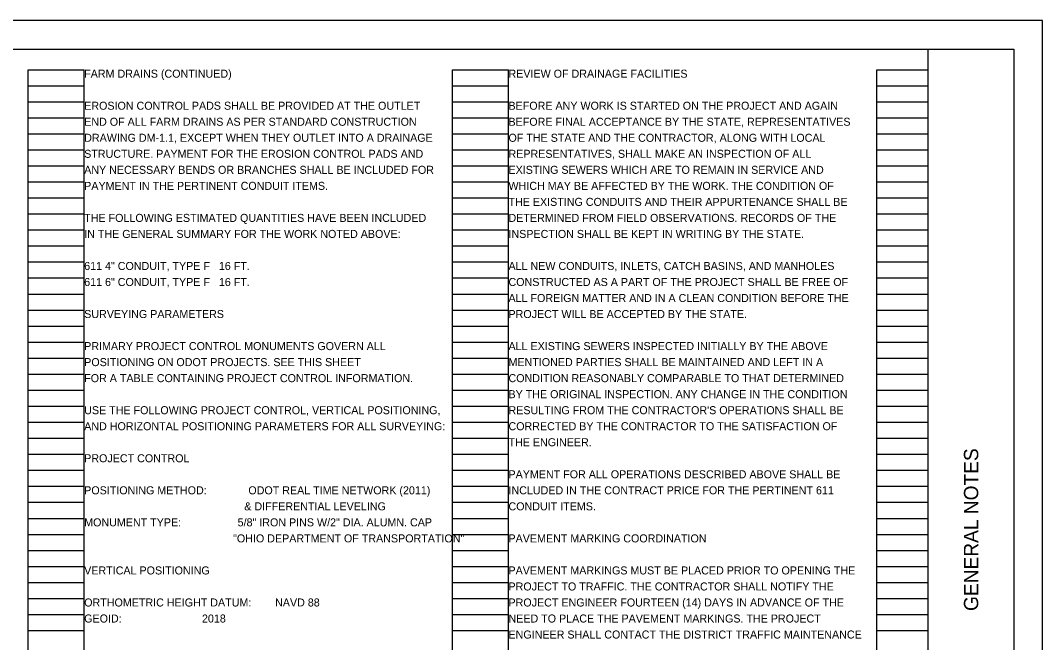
# Model space of a CAD drawing. Extents: x 0 to 34, y 0 to 22.
# Drawn here: x 16.13 to 34, y 11.13 to 22 of the extents above; entities that cross this region are included whole.
import ezdxf

# ---------------------------------------------------------------- set-up
doc = ezdxf.new("R2010")
doc.units = 0
for name, color, linetype in [('SH_Border', 7, 'Continuous'), ('SH_Cut_Line', 7, 'Continuous'), ('SH_Data', 7, 'Continuous'), ('SH_Text', 7, 'Continuous')]:
    doc.layers.add(name, color=color, linetype=linetype)

msp = doc.modelspace()

# ---------------------------------------------------------------- linework, layer by layer
at = {"layer": 'SH_Border'}
msp.add_line((32, 0.5), (32, 21.5), dxfattribs=at)
msp.add_lwpolyline([(1.5, 21.5), (33.5, 21.5), (33.5, 0.5), (1.5, 0.5)], close=True, dxfattribs=at)
at = {"layer": 'SH_Cut_Line'}
msp.add_lwpolyline([(0, 0), (34, 0), (34, 22), (0, 22)], close=True, dxfattribs=at)
at = {"layer": 'SH_Data'}
for p, q in [((16.26, 0.98), (16.26, 21.14)), ((16.26, 21.14), (17.24, 21.14)), ((17.24, 0.98), (17.24, 21.14)), ((23.68, 0.98), (23.68, 21.14)), ((23.68, 21.14), (24.66, 21.14)), ((24.66, 0.98), (24.66, 21.14)), ((31.1, 0.98), (31.1, 21.14)), ((31.1, 21.14), (32, 21.14)), ((32, 0.98), (32, 21.14)), ((16.26, 20.86), (17.24, 20.86)), ((23.68, 20.86), (24.66, 20.86)), ((31.1, 20.86), (32, 20.86)), ((16.26, 20.58), (17.24, 20.58)), ((23.68, 20.58), (24.66, 20.58)), ((31.1, 20.58), (32, 20.58)), ((16.26, 20.3), (17.24, 20.3)), ((23.68, 20.3), (24.66, 20.3)), ((31.1, 20.3), (32, 20.3)), ((16.26, 20.02), (17.24, 20.02)), ((23.68, 20.02), (24.66, 20.02)), ((31.1, 20.02), (32, 20.02)), ((16.26, 19.74), (17.24, 19.74)), ((23.68, 19.74), (24.66, 19.74)), ((31.1, 19.74), (32, 19.74)), ((16.26, 19.46), (17.24, 19.46)), ((23.68, 19.46), (24.66, 19.46)), ((31.1, 19.46), (32, 19.46)), ((16.26, 19.18), (17.24, 19.18)), ((23.68, 19.18), (24.66, 19.18)), ((31.1, 19.18), (32, 19.18)), ((16.26, 18.9), (17.24, 18.9)), ((23.68, 18.9), (24.66, 18.9)), ((31.1, 18.9), (32, 18.9)), ((16.26, 18.62), (17.24, 18.62)), ((23.68, 18.62), (24.66, 18.62)), ((31.1, 18.62), (32, 18.62)), ((16.26, 18.34), (17.24, 18.34)), ((23.68, 18.34), (24.66, 18.34)), ((31.1, 18.34), (32, 18.34)), ((16.26, 18.06), (17.24, 18.06)), ((23.68, 18.06), (24.66, 18.06)), ((31.1, 18.06), (32, 18.06)), ((16.26, 17.78), (17.24, 17.78)), ((23.68, 17.78), (24.66, 17.78)), ((31.1, 17.78), (32, 17.78)), ((16.26, 17.5), (17.24, 17.5)), ((23.68, 17.5), (24.66, 17.5)), ((31.1, 17.5), (32, 17.5)), ((16.26, 17.22), (17.24, 17.22)), ((23.68, 17.22), (24.66, 17.22)), ((31.1, 17.22), (32, 17.22)), ((16.26, 16.94), (17.24, 16.94)), ((23.68, 16.94), (24.66, 16.94)), ((31.1, 16.94), (32, 16.94)), ((16.26, 16.66), (17.24, 16.66)), ((23.68, 16.66), (24.66, 16.66)), ((31.1, 16.66), (32, 16.66)), ((16.26, 16.38), (17.24, 16.38)), ((23.68, 16.38), (24.66, 16.38)), ((31.1, 16.38), (32, 16.38)), ((16.26, 16.1), (17.24, 16.1)), ((23.68, 16.1), (24.66, 16.1)), ((31.1, 16.1), (32, 16.1)), ((16.26, 15.82), (17.24, 15.82)), ((23.68, 15.82), (24.66, 15.82)), ((31.1, 15.82), (32, 15.82)), ((16.26, 15.54), (17.24, 15.54)), ((23.68, 15.54), (24.66, 15.54)), ((31.1, 15.54), (32, 15.54)), ((16.26, 15.26), (17.24, 15.26)), ((23.68, 15.26), (24.66, 15.26)), ((31.1, 15.26), (32, 15.26)), ((16.26, 14.98), (17.24, 14.98)), ((23.68, 14.98), (24.66, 14.98)), ((31.1, 14.98), (32, 14.98)), ((16.26, 14.7), (17.24, 14.7)), ((23.68, 14.7), (24.66, 14.7)), ((31.1, 14.7), (32, 14.7)), ((16.26, 14.42), (17.24, 14.42)), ((23.68, 14.42), (24.66, 14.42)), ((31.1, 14.42), (32, 14.42)), ((16.26, 14.14), (17.24, 14.14)), ((23.68, 14.14), (24.66, 14.14)), ((31.1, 14.14), (32, 14.14)), ((16.26, 13.86), (17.24, 13.86)), ((23.68, 13.86), (24.66, 13.86)), ((31.1, 13.86), (32, 13.86)), ((16.26, 13.58), (17.24, 13.58)), ((23.68, 13.58), (24.66, 13.58)), ((31.1, 13.58), (32, 13.58)), ((16.26, 13.3), (17.24, 13.3)), ((23.68, 13.3), (24.66, 13.3)), ((31.1, 13.3), (32, 13.3)), ((16.26, 13.02), (17.24, 13.02)), ((23.68, 13.02), (24.66, 13.02)), ((31.1, 13.02), (32, 13.02)), ((16.26, 12.74), (17.24, 12.74)), ((23.68, 12.74), (24.66, 12.74)), ((31.1, 12.74), (32, 12.74)), ((16.26, 12.46), (17.24, 12.46)), ((23.68, 12.46), (24.66, 12.46)), ((31.1, 12.46), (32, 12.46)), ((16.26, 12.18), (17.24, 12.18)), ((23.68, 12.18), (24.66, 12.18)), ((31.1, 12.18), (32, 12.18)), ((16.26, 11.9), (17.24, 11.9)), ((23.68, 11.9), (24.66, 11.9)), ((31.1, 11.9), (32, 11.9)), ((16.26, 11.62), (17.24, 11.62)), ((23.68, 11.62), (24.66, 11.62)), ((31.1, 11.62), (32, 11.62)), ((16.26, 11.34), (17.24, 11.34)), ((23.68, 11.34), (24.66, 11.34)), ((31.1, 11.34), (32, 11.34))]:
    msp.add_line(p, q, dxfattribs=at)

# ---------------------------------------------------------------- texts
msp.add_text('GENERAL NOTES', height=0.25, rotation=90, dxfattribs=at).set_placement((32.875, 11.682))
at = {"layer": 'SH_Text'}
for s, p in [('FARM DRAINS (CONTINUED)', (17.24, 21)), ('REVIEW OF DRAINAGE FACILITIES', (24.66, 21)), ('EROSION CONTROL PADS SHALL BE PROVIDED AT THE OUTLET', (17.24, 20.44)), ('BEFORE ANY WORK IS STARTED ON THE PROJECT AND AGAIN', (24.66, 20.44)), ('END OF ALL FARM DRAINS AS PER STANDARD CONSTRUCTION', (17.24, 20.16)), ('BEFORE FINAL ACCEPTANCE BY THE STATE, REPRESENTATIVES', (24.66, 20.16)), ('DRAWING DM-1.1, EXCEPT WHEN THEY OUTLET INTO A DRAINAGE', (17.24, 19.88)), ('OF THE STATE AND THE CONTRACTOR, ALONG WITH LOCAL', (24.66, 19.88)), ('STRUCTURE. PAYMENT FOR THE EROSION CONTROL PADS AND', (17.24, 19.6)), ('REPRESENTATIVES, SHALL MAKE AN INSPECTION OF ALL', (24.66, 19.6)), ('ANY NECESSARY BENDS OR BRANCHES SHALL BE INCLUDED FOR', (17.24, 19.32)), ('EXISTING SEWERS WHICH ARE TO REMAIN IN SERVICE AND', (24.66, 19.32)), ('PAYMENT IN THE PERTINENT CONDUIT ITEMS.', (17.24, 19.04)), ('WHICH MAY BE AFFECTED BY THE WORK. THE CONDITION OF', (24.66, 19.04)), ('THE EXISTING CONDUITS AND THEIR APPURTENANCE SHALL BE', (24.66, 18.76)), ('THE FOLLOWING ESTIMATED QUANTITIES HAVE BEEN INCLUDED', (17.24, 18.48)), ('DETERMINED FROM FIELD OBSERVATIONS. RECORDS OF THE', (24.66, 18.48)), ('IN THE GENERAL SUMMARY FOR THE WORK NOTED ABOVE:', (17.24, 18.2)), ('INSPECTION SHALL BE KEPT IN WRITING BY THE STATE.', (24.66, 18.2)), ('611 4" CONDUIT, TYPE F   16 FT.', (17.24, 17.64)), ('ALL NEW CONDUITS, INLETS, CATCH BASINS, AND MANHOLES', (24.66, 17.64)), ('611 6" CONDUIT, TYPE F   16 FT.', (17.24, 17.36)), ('CONSTRUCTED AS A PART OF THE PROJECT SHALL BE FREE OF', (24.66, 17.36)), ('ALL FOREIGN MATTER AND IN A CLEAN CONDITION BEFORE THE', (24.66, 17.08)), ('SURVEYING PARAMETERS', (17.24, 16.8)), ('PROJECT WILL BE ACCEPTED BY THE STATE.', (24.66, 16.8)), ('PRIMARY PROJECT CONTROL MONUMENTS GOVERN ALL', (17.24, 16.24)), ('ALL EXISTING SEWERS INSPECTED INITIALLY BY THE ABOVE', (24.66, 16.24)), ('POSITIONING ON ODOT PROJECTS. SEE THIS SHEET', (17.24, 15.96)), ('MENTIONED PARTIES SHALL BE MAINTAINED AND LEFT IN A', (24.66, 15.96)), ('FOR A TABLE CONTAINING PROJECT CONTROL INFORMATION.', (17.24, 15.68)), ('CONDITION REASONABLY COMPARABLE TO THAT DETERMINED', (24.66, 15.68)), ('BY THE ORIGINAL INSPECTION. ANY CHANGE IN THE CONDITION', (24.66, 15.4)), ('USE THE FOLLOWING PROJECT CONTROL, VERTICAL POSITIONING,', (17.24, 15.12)), ("RESULTING FROM THE CONTRACTOR'S OPERATIONS SHALL BE", (24.66, 15.12)), ('AND HORIZONTAL POSITIONING PARAMETERS FOR ALL SURVEYING:', (17.24, 14.84)), ('CORRECTED BY THE CONTRACTOR TO THE SATISFACTION OF', (24.66, 14.84)), ('THE ENGINEER.', (24.66, 14.56)), ('PROJECT CONTROL', (17.24, 14.28)), ('PAYMENT FOR ALL OPERATIONS DESCRIBED ABOVE SHALL BE', (24.66, 14)), ('POSITIONING METHOD:              ODOT REAL TIME NETWORK (2011)', (17.24, 13.72)), ('INCLUDED IN THE CONTRACT PRICE FOR THE PERTINENT 611', (24.66, 13.72)), ('& DIFFERENTIAL LEVELING', (20.04, 13.44)), ('CONDUIT ITEMS.', (24.66, 13.44)), ('MONUMENT TYPE:                   5/8" IRON PINS W/2" DIA. ALUMN. CAP', (17.24, 13.16)), ('       "OHIO DEPARTMENT OF TRANSPORTATION"', (19.48, 12.88)), ('PAVEMENT MARKING COORDINATION', (24.66, 12.88)), ('VERTICAL POSITIONING', (17.24, 12.32)), ('PAVEMENT MARKINGS MUST BE PLACED PRIOR TO OPENING THE', (24.66, 12.32)), ('PROJECT TO TRAFFIC. THE CONTRACTOR SHALL NOTIFY THE', (24.66, 12.04)), ('ORTHOMETRIC HEIGHT DATUM:        NAVD 88', (17.24, 11.76)), ('PROJECT ENGINEER FOURTEEN (14) DAYS IN ADVANCE OF THE', (24.66, 11.76)), ('GEOID:                           2018', (17.24, 11.48)), ('NEED TO PLACE THE PAVEMENT MARKINGS. THE PROJECT', (24.66, 11.48)), ('ENGINEER SHALL CONTACT THE DISTRICT TRAFFIC MAINTENANCE', (24.66, 11.2))]:
    msp.add_text(s, height=0.14, dxfattribs=at).set_placement(p)

doc.saveas('drawing.dxf')
